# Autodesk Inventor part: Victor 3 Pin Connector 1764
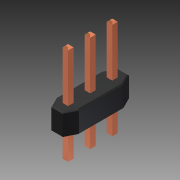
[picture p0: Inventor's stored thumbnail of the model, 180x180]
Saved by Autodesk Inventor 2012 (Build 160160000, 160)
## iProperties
Shininess: 64.0
Length Units: 11272
Angle Units: 11279
Time Units: 11290
Mass Units: 11286
Length Display Precision: 3
Angle Display Precision: 2
Compacted: True
Part Number: Victor 3 Pin Connector 1764
Document SubType Name: Modeling
Created: 2005-12
Designer: Owner
Material: ABS Plastic
Density: 1 g/cm^3
Density: 0.0
Volumn: 0.0
Area: 0.0
PropertySet Name: Model Information
Control State: 0
Master: False
Checked Out: False
Author: Owner
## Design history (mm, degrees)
sketch "Sketch1"
  geometry: L1 (0, 0)-(2.54, 0); L2 (2.54, 0)-(2.54, 7.62); L3 (2.54, 7.62)-(0, 7.62); L4 (0, 7.62)-(0, 0); L5 (0.953, 4.128)-(1.587, 4.128); L6 (1.587, 4.128)-(1.587, 3.493); L7 (1.587, 3.493)-(0.953, 3.493); L8 (0.953, 3.493)-(0.953, 4.128); L9 (0.953, 1.587)-(1.587, 1.587); L10 (1.587, 1.587)-(1.587, 0.953); L11 (1.587, 0.953)-(0.953, 0.953); L12 (0.953, 0.953)-(0.953, 1.587); L13 (0.953, 3.81)-(0, 3.81); L14 (1.587, 1.27)-(2.54, 1.27); L15 (0.953, 6.033)-(1.587, 6.033); L16 (1.587, 6.033)-(1.587, 6.667); L17 (1.587, 6.667)-(0.953, 6.667); L18 (0.953, 6.667)-(0.953, 6.033)
  constraints: 36 end point, 8 parallel, 6 equal length, 6 perpendicular, 4 horizontal, 3 midpoint, 2 collinear, 1 point on line, 1 other
  dimensions: "d3" = 2.54 distance of L1.start L1.end; "d4" = 7.62 distance of L3.end L1.start; "d5" = 0.635 distance of L5.end L6.end; "d6" = 2.54 distance between parallel lines of L11 L7; "d7" = 0.9525 distance between parallel lines of L1 L11; "d25" = 2.54 distance between parallel lines of L17 L5
extrude "Extrusion1" new body sketch "Sketch1" distance "d8" = 2.54; taper "d9" = 0 deg
chamfer "Chamfer1" distance "d10" = 1.27; stored, may be unused: second distance "d11" = 0.635, angle "d26" = 45 deg
chamfer "Chamfer2" distance "d12" = 1.27; stored, may be unused: second distance "d13" = 0.635, angle "d27" = 45 deg
chamfer "Chamfer3" distance "d14" = 1.27; stored, may be unused: second distance "d15" = 0.635, angle "d28" = 45 deg
chamfer "Chamfer4" distance "d16" = 1.27; stored, may be unused: second distance "d17" = 0.635, angle "d29" = 45 deg
workplane "Work Plane1"
sketch "Sketch2"
  geometry: L1 (-1.587, 4.128)-(-0.953, 4.128) reference; L2 (-1.587, 3.493)-(-1.587, 4.128) reference; L3 (-0.953, 4.128)-(-0.953, 3.493) reference; L4 (-0.953, 3.493)-(-1.587, 3.493) reference; L5 (-1.587, 1.587)-(-0.953, 1.587) reference; L6 (-0.953, 1.587)-(-0.953, 0.953) reference; L7 (-0.953, 0.953)-(-1.587, 0.953) reference; L8 (-1.587, 0.953)-(-1.587, 1.587) reference; L9 (-0.953, 6.667)-(-0.953, 6.033) reference; L10 (-0.953, 6.033)-(-1.587, 6.033) reference; L11 (-1.587, 6.033)-(-1.587, 6.667) reference; L12 (-1.587, 6.667)-(-0.953, 6.667) reference
extrude "Extrusion2" join sketch "Sketch2" distance "d19" = 11.43; taper "d20" = 0 deg
chamfer "Chamfer5" distance "d21" = 0.1778; stored, may be unused: second distance "d22" = 0.635, angle "d30" = 45 deg
chamfer "Chamfer6" distance "d23" = 0.127; stored, may be unused: second distance "d24" = 0.635, angle "d31" = 45 deg
body "Solid1"
other parameters: "d18" = 3.175
